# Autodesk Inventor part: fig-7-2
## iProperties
Created: 2004-05
Part Number: fig-7-2
Document SubType Name: Modeling
Designer: CADCIM Technologies
Manufacturer: Standard
Standards Organization: Custom
Density: 1 g/cm^3
Author: CADCIM Technologies
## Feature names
1. Sweep4
